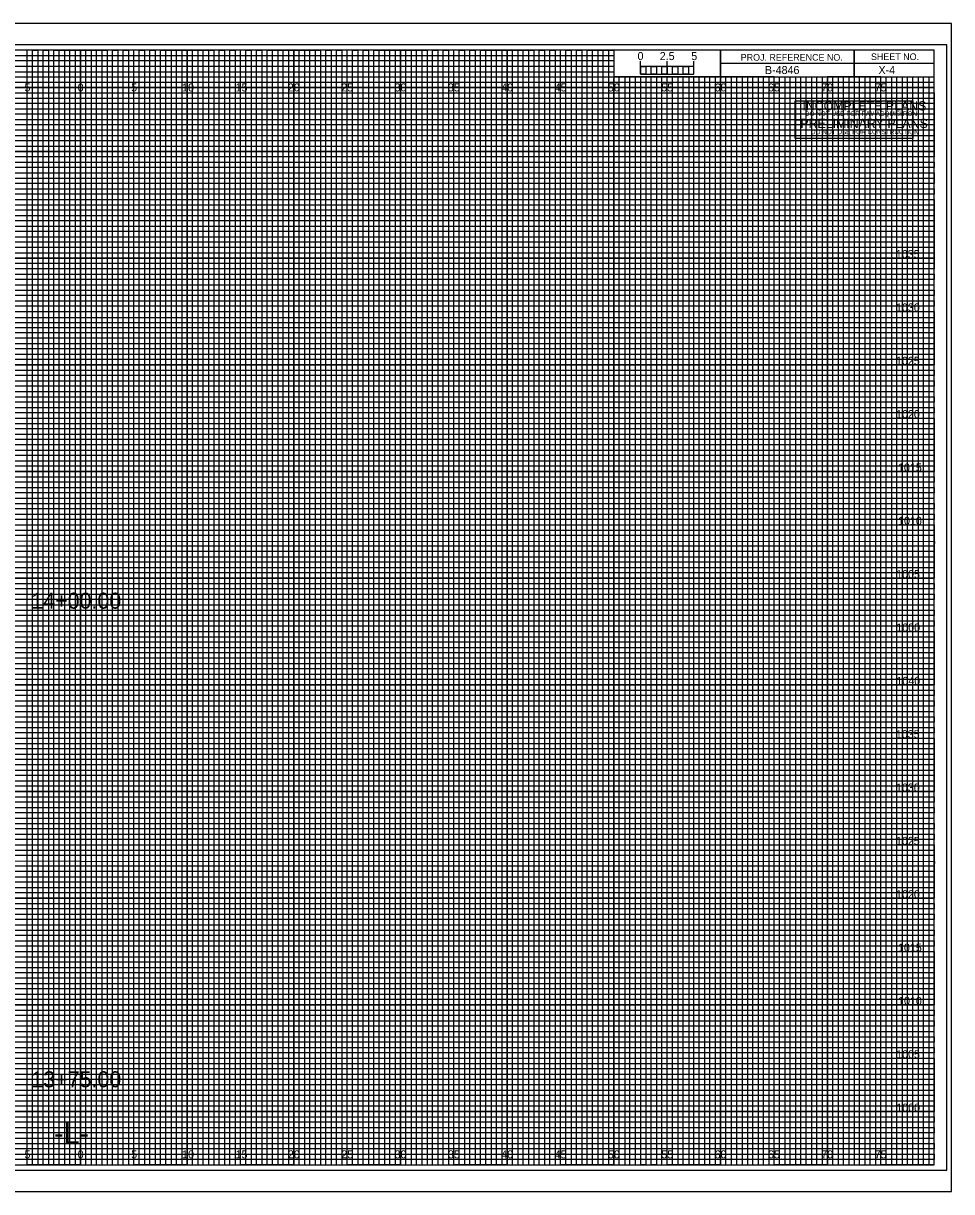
# Model space of a CAD drawing. Extents: x -7 to 162, y -2 to 987.
# Drawn here: x 74.6 to 161.7, y 327.5 to 437 of the extents above; entities that cross this region are included whole.
import ezdxf

# ---------------------------------------------------------------- set-up
doc = ezdxf.new("R2010")
doc.units = 0
for name, color, linetype in [('Default', 7, 'Continuous'), ('Exist Cross Section Cell', 7, 'Continuous'), ('Exist XS Center Line Elevation Label', 7, 'Continuous'), ('Exist XS Ground Line', 7, 'Continuous'), ('Prop CMT Concrete Structures', 7, 'Continuous'), ('Prop CMT DNC', 7, 'Continuous'), ('Prop CMT Guardrail Graphics', 7, 'Continuous'), ('Prop CMT Guardrail Widen Shoulder', 7, 'Continuous'), ('Prop CMT Pvmt Course 1', 7, 'Continuous'), ('Prop CMT Pvmt Surface', 7, 'Continuous'), ('Prop CMT Pvmt Surface Shoulder', 7, 'Continuous'), ('Prop CMT Shld Paved Course 1', 7, 'Continuous'), ('Prop CMT Shoulder Point', 7, 'Continuous'), ('Prop CMT Slope Grass', 7, 'Continuous'), ('Prop CMT Subgrade Earthwork', 7, 'Continuous'), ('Prop XS SE Text', 7, 'Continuous'), ('Prop XS Side Slope Text', 7, 'Continuous'), ('Typical Text Label CELL', 7, 'Continuous')]:
    doc.layers.add(name, color=color, linetype=linetype)

msp = doc.modelspace()

# ---------------------------------------------------------------- linework, layer by layer
at = {"layer": 'Default'}
for points in [[(146.99, 427.97), (146.99, 429.73), (158.01, 429.73), (158.01, 427.97)], [(146.99, 426.2), (146.99, 427.97), (158.01, 427.97), (158.01, 426.2)]]:
    msp.add_lwpolyline(points, close=True, dxfattribs=at)
at = {"layer": 'Exist XS Center Line Elevation Label'}
for points in [[(72.5, 330), (77.5, 330), (77.5, 434.5), (82.5, 434.5), (82.5, 330), (87.5, 330), (87.5, 434.5), (92.5, 434.5), (92.5, 330), (97.5, 330), (97.5, 434.5), (102.5, 434.5), (102.5, 330), (107.5, 330), (107.5, 434.5), (112.5, 434.5), (112.5, 330), (117.5, 330), (117.5, 434.5), (122.5, 434.5), (122.5, 330), (127.5, 330), (127.5, 434.5), (129.97, 434.5), (130, 434.5), (130, 432), (132.5, 432), (132.5, 330), (137.5, 330), (137.5, 432), (142.5, 432), (142.5, 330), (147.5, 330), (147.5, 432), (152.5, 432), (152.5, 330), (157.5, 330), (157.5, 432)], [(0, 432), (137.5, 432)], [(0, 422.5), (160, 422.5), (160, 427.5), (0, 427.5)], [(0, 412.5), (160, 412.5), (160, 417.5), (0, 417.5)], [(0, 402.5), (160, 402.5), (160, 407.5), (0, 407.5)], [(0, 392.5), (160, 392.5), (160, 397.5), (0, 397.5)], [(0, 382.5), (160, 382.5), (160, 387.5), (0, 387.5)], [(0, 372.5), (160, 372.5), (160, 377.5), (0, 377.5)], [(0, 362.5), (160, 362.5), (160, 367.5), (0, 367.5)], [(0, 352.5), (160, 352.5), (160, 357.5), (0, 357.5)], [(0, 342.5), (160, 342.5), (160, 347.5), (0, 347.5)], [(0, 332.5), (160, 332.5), (160, 337.5), (0, 337.5)]]:
    msp.add_lwpolyline(points, dxfattribs=at)
at = {"layer": 'Exist XS Ground Line'}
for p, q in [((75, 434.5), (70, 434.5)), ((75, 330), (75, 434.5)), ((85, 434.5), (80, 434.5)), ((80, 434.5), (80, 330)), ((85, 330), (85, 434.5)), ((95, 434.5), (90, 434.5)), ((90, 434.5), (90, 330)), ((95, 330), (95, 434.5)), ((105, 434.5), (100, 434.5)), ((100, 434.5), (100, 330)), ((105, 330), (105, 434.5)), ((115, 434.5), (110, 434.5)), ((110, 434.5), (110, 330)), ((115, 330), (115, 434.5)), ((125, 434.5), (120, 434.5)), ((120, 434.5), (120, 330)), ((125, 330), (125, 434.5)), ((130, 434.5), (130, 330)), ((135, 330), (135, 432)), ((145, 432), (140, 432)), ((140, 432), (140, 330)), ((145, 330), (145, 432)), ((155, 432), (150, 432)), ((150, 432), (150, 330)), ((155, 330), (155, 432)), ((80, 330), (75, 330)), ((90, 330), (85, 330)), ((100, 330), (95, 330)), ((110, 330), (105, 330)), ((120, 330), (115, 330)), ((130, 330), (125, 330)), ((140, 330), (135, 330)), ((150, 330), (145, 330)), ((160, 330), (155, 330)), ((160, 330), (160, 330))]:
    msp.add_line(p, q, dxfattribs=at)
for points in [[(0, 430), (160, 430), (160, 425), (0, 425)], [(0, 420), (160, 420), (160, 415), (0, 415)], [(0, 410), (160, 410), (160, 405), (0, 405)], [(0, 400), (160, 400), (160, 395), (0, 395)], [(0, 390), (160, 390), (160, 385), (0, 385)], [(0, 380), (160, 380), (160, 375), (0, 375)], [(0, 370), (160, 370), (160, 365), (0, 365)], [(0, 360), (160, 360), (160, 355), (0, 355)], [(0, 350), (160, 350), (160, 345), (0, 345)], [(0, 340), (160, 340), (160, 335), (0, 335)]]:
    msp.add_lwpolyline(points, dxfattribs=at)
at = {"layer": 'Prop CMT Concrete Structures'}
for p, q in [((75, 330), (75, 434.5)), ((80, 330), (80, 434.5)), ((85, 330), (85, 434.5)), ((90, 330), (90, 434.5)), ((95, 330), (95, 434.5)), ((100, 330), (100, 434.5)), ((105, 330), (105, 434.5)), ((110, 330), (110, 434.5)), ((115, 330), (115, 434.5)), ((120, 330), (120, 434.5)), ((125, 330), (125, 434.5)), ((130, 330), (130, 431.84)), ((135, 330), (135, 431.84)), ((140, 330), (140, 431.84)), ((145, 330), (145, 431.84)), ((150, 330), (150, 431.84)), ((155, 330), (155, 431.84)), ((0, 430), (160, 430)), ((0, 425), (160, 425)), ((0, 420), (160, 420)), ((0, 415), (160, 415)), ((0, 410), (160, 410)), ((0, 405), (160, 405)), ((0, 400), (160, 400)), ((0, 395), (160, 395)), ((0, 390), (160, 390)), ((0, 385), (160, 385)), ((0, 380), (160, 380)), ((0, 375), (160, 375)), ((0, 370), (160, 370)), ((0, 365), (160, 365)), ((0, 360), (160, 360)), ((0, 355), (160, 355)), ((0, 350), (160, 350)), ((0, 345), (160, 345)), ((0, 340), (160, 340)), ((0, 335), (160, 335))]:
    msp.add_line(p, q, dxfattribs=at)
at = {"layer": 'Prop CMT Guardrail Widen Shoulder'}
for p, q in [((161.65, 437), (-6.7, 437)), ((-6.7, 327.5), (161.65, 327.5))]:
    msp.add_line(p, q, dxfattribs=at)
at = {"layer": 'Prop CMT Pvmt Course 1'}
msp.add_lwpolyline([(-6.7, 327.5), (161.65, 327.5), (161.65, 437), (-6.7, 437)], close=True, dxfattribs=at)
at = {"layer": 'Prop CMT Pvmt Surface'}
for p, q in [((133.5, 432), (133, 432)), ((133, 432), (133, 330)), ((133.5, 330), (133.5, 432)), ((134.5, 432), (134, 432)), ((134, 432), (134, 330)), ((134.5, 330), (134.5, 432)), ((133, 330), (132.5, 330)), ((134, 330), (133.5, 330))]:
    msp.add_line(p, q, dxfattribs=at)
for points in [[(75, 330), (75.5, 330), (75.5, 434.5), (76, 434.5), (76, 330)], [(76, 330), (76.5, 330), (76.5, 434.5), (77, 434.5), (77, 330)], [(77.5, 330), (78, 330), (78, 434.5), (78.5, 434.5), (78.5, 330)], [(78.5, 330), (79, 330), (79, 434.5), (79.5, 434.5), (79.5, 330)], [(80, 330), (80.5, 330), (80.5, 434.5), (81, 434.5), (81, 330)], [(81, 330), (81.5, 330), (81.5, 434.5), (82, 434.5), (82, 330)], [(82.5, 330), (83, 330), (83, 434.5), (83.5, 434.5), (83.5, 330)], [(83.5, 330), (84, 330), (84, 434.5), (84.5, 434.5), (84.5, 330)], [(85, 330), (85.5, 330), (85.5, 434.5), (86, 434.5), (86, 330)], [(86, 330), (86.5, 330), (86.5, 434.5), (87, 434.5), (87, 330)], [(87.5, 330), (88, 330), (88, 434.5), (88.5, 434.5), (88.5, 330)], [(88.5, 330), (89, 330), (89, 434.5), (89.5, 434.5), (89.5, 330)], [(90, 330), (90.5, 330), (90.5, 434.5), (91, 434.5), (91, 330)], [(91, 330), (91.5, 330), (91.5, 434.5), (92, 434.5), (92, 330)], [(92.5, 330), (93, 330), (93, 434.5), (93.5, 434.5), (93.5, 330)], [(93.5, 330), (94, 330), (94, 434.5), (94.5, 434.5), (94.5, 330)], [(95, 330), (95.5, 330), (95.5, 434.5), (96, 434.5), (96, 330)], [(96, 330), (96.5, 330), (96.5, 434.5), (97, 434.5), (97, 330)], [(97.5, 330), (98, 330), (98, 434.5), (98.5, 434.5), (98.5, 330)], [(98.5, 330), (99, 330), (99, 434.5), (99.5, 434.5), (99.5, 330)], [(100, 330), (100.5, 330), (100.5, 434.5), (101, 434.5), (101, 330)], [(101, 330), (101.5, 330), (101.5, 434.5), (102, 434.5), (102, 330)], [(102.5, 330), (103, 330), (103, 434.5), (103.5, 434.5), (103.5, 330)], [(103.5, 330), (104, 330), (104, 434.5), (104.5, 434.5), (104.5, 330)], [(105, 330), (105.5, 330), (105.5, 434.5), (106, 434.5), (106, 330)], [(106, 330), (106.5, 330), (106.5, 434.5), (107, 434.5), (107, 330)], [(107.5, 330), (108, 330), (108, 434.5), (108.5, 434.5), (108.5, 330)], [(108.5, 330), (109, 330), (109, 434.5), (109.5, 434.5), (109.5, 330)], [(110, 330), (110.5, 330), (110.5, 434.5), (111, 434.5), (111, 330)], [(111, 330), (111.5, 330), (111.5, 434.5), (112, 434.5), (112, 330)], [(112.5, 330), (113, 330), (113, 434.5), (113.5, 434.5), (113.5, 330)], [(113.5, 330), (114, 330), (114, 434.5), (114.5, 434.5), (114.5, 330)], [(115, 330), (115.5, 330), (115.5, 434.5), (116, 434.5), (116, 330)], [(116, 330), (116.5, 330), (116.5, 434.5), (117, 434.5), (117, 330)], [(117.5, 330), (118, 330), (118, 434.5), (118.5, 434.5), (118.5, 330)], [(118.5, 330), (119, 330), (119, 434.5), (119.5, 434.5), (119.5, 330)], [(120, 330), (120.5, 330), (120.5, 434.5), (121, 434.5), (121, 330)], [(121, 330), (121.5, 330), (121.5, 434.5), (122, 434.5), (122, 330)], [(122.5, 330), (123, 330), (123, 434.5), (123.5, 434.5), (123.5, 330)], [(123.5, 330), (124, 330), (124, 434.5), (124.5, 434.5), (124.5, 330)], [(125, 330), (125.5, 330), (125.5, 434.5), (126, 434.5), (126, 330)], [(126, 330), (126.5, 330), (126.5, 434.5), (127, 434.5), (127, 330)], [(127.5, 330), (128, 330), (128, 434.5), (128.5, 434.5), (128.5, 330)], [(128.5, 330), (129, 330), (129, 434.5), (129.5, 434.5), (129.5, 330)], [(130, 330), (130.5, 330), (130.5, 432), (131.01, 432), (131.01, 330)], [(131, 330), (131.5, 330), (131.5, 432), (132, 432), (132, 330)], [(135, 330), (135.49, 330), (135.49, 432), (136, 432), (136, 330)], [(136, 330), (136.5, 330), (136.5, 432), (137.03, 432), (137.03, 330)], [(137.5, 330), (138, 330), (138, 432), (138.5, 432), (138.5, 330)], [(138.5, 330), (139, 330), (139, 432), (139.5, 432), (139.5, 330)], [(140, 330), (140.5, 330), (140.5, 432), (141, 432), (141, 330)], [(141, 330), (141.5, 330), (141.5, 432), (142, 432), (142, 330)], [(142.5, 330), (143, 330), (143, 432), (143.5, 432), (143.5, 330)], [(143.5, 330), (144, 330), (144, 432), (144.5, 432), (144.5, 330)], [(145, 330), (145.5, 330), (145.5, 432), (146, 432), (146, 330)], [(146, 330), (146.5, 330), (146.5, 432), (147, 432), (147, 330)], [(147.5, 330), (148, 330), (148, 432), (148.5, 432), (148.5, 330)], [(148.5, 330), (149, 330), (149, 432), (149.5, 432), (149.5, 330)], [(150, 330), (150.5, 330), (150.5, 432), (151, 432), (151, 330)], [(151, 330), (151.5, 330), (151.5, 432), (152, 432), (152, 330)], [(152.5, 330), (153, 330), (153, 432), (153.5, 432), (153.5, 330)], [(153.5, 330), (154, 330), (154, 432), (154.5, 432), (154.5, 330)], [(155, 330), (155.5, 330), (155.5, 432), (156, 432), (156, 330)], [(156, 330), (156.5, 330), (156.5, 432), (157, 432), (157, 330)], [(157.5, 330), (158, 330), (158, 432), (158.5, 432), (158.5, 330)], [(158.5, 330), (159, 330), (159, 432), (159.5, 432), (159.5, 330)]]:
    msp.add_lwpolyline(points, dxfattribs=at)
at = {"layer": 'Prop CMT Pvmt Surface Shoulder'}
for p, q in [((132.5, 432.25), (132.5, 433.45)), ((132.5, 432.95), (132.5, 433.45)), ((135, 432.25), (135, 433.45)), ((137.5, 432.25), (137.5, 433.45)), ((137.5, 432.95), (137.5, 433.45))]:
    msp.add_line(p, q, dxfattribs=at)
for points in [[(137.5, 432.95), (132.5, 432.95), (132.5, 432.25), (137.5, 432.25)], [(132.5, 432.95), (133, 432.95), (133, 432.25), (132.5, 432.25)], [(133.5, 432.95), (134, 432.95), (134, 432.25), (133.5, 432.25)], [(134.5, 432.95), (135, 432.95), (135, 432.25), (134.5, 432.25)], [(135.5, 432.95), (136, 432.95), (136, 432.25), (135.5, 432.25)], [(136.5, 432.95), (137, 432.95), (137, 432.25), (136.5, 432.25)]]:
    msp.add_lwpolyline(points, close=True, dxfattribs=at)
at = {"layer": 'Prop CMT Shld Paved Course 1'}
for p, q in [((0, 434), (130, 434)), ((130, 434), (130, 433.49)), ((130, 433.49), (0, 433.49)), ((0, 433), (130, 433)), ((130, 433), (130, 432.44)), ((130, 432.44), (0, 432.44)), ((0, 431.5), (160, 431.5))]:
    msp.add_line(p, q, dxfattribs=at)
for points in [[(0, 431), (135, 431), (160, 431), (160, 431), (0, 431)], [(0, 430.5), (160, 430.5), (160, 429.5), (0, 429.5)], [(0, 429), (160, 429), (160, 428.5), (0, 428.49)], [(0, 428), (160, 428), (160, 427), (0, 427)], [(0, 426.5), (160, 426.5), (160, 426), (0, 426)], [(0, 425.5), (160, 425.5), (160, 424.5), (0, 424.5)], [(0, 424), (160, 424), (160, 423.5), (0, 423.5)], [(0, 423), (160, 423), (160, 422), (0, 422)], [(0, 421.5), (160, 421.5), (160, 421), (0, 421)], [(0, 420.5), (160, 420.5), (160, 419.5), (0, 419.5)], [(0, 419), (160, 419), (160, 418.5), (0, 418.5)], [(0, 418), (160, 418), (160, 416.98), (160, 416.5), (160, 416), (0, 416)], [(0, 417), (160, 417), (160, 416.5), (0, 416.5)], [(0, 415.5), (160, 415.5), (160, 414.5), (0, 414.51)], [(0, 414.51), (160, 414.5), (160, 414), (0, 414)], [(0, 413.5), (160, 413.5), (160, 413), (0, 413)], [(0, 412), (160, 412), (160, 411.5), (0, 411.5)], [(0, 411), (160, 411), (160, 410.5), (0, 410.5)], [(-0.04, 409.44), (160, 409.44), (160, 408.94), (-0.04, 408.94)], [(0, 408.5), (160, 408.5), (160, 408), (0, 408)], [(0, 407), (160, 407), (160, 406.5), (0, 406.5)], [(0, 406), (160, 406), (160, 405.5), (0, 405.5)], [(0, 404.5), (160, 404.5), (160, 404), (0, 404)], [(0, 403.5), (160, 403.5), (160, 403), (0, 403)], [(0, 402), (160, 402), (160, 401.5), (0, 401.5)], [(0, 401), (160, 401), (160, 400.5), (0, 400.5)], [(0, 399.5), (160, 399.5), (160, 398.99), (0, 399)], [(0, 398.5), (160, 398.5), (160, 398), (0, 398)], [(0, 397), (160, 397), (160, 396.5), (0, 396.5)], [(0, 396), (160, 396), (160, 395.5), (0, 395.5)], [(0, 394.5), (160, 394.5), (160, 394), (0, 394)], [(0, 393.5), (160, 393.5), (160, 393), (0, 393)], [(0, 392), (160, 392), (160, 391.5), (0, 391.5)], [(0, 391), (160, 391), (160, 390.5), (0, 390.5)], [(0, 389.5), (160, 389.5), (160, 389), (0, 389)], [(0, 388.5), (160.03, 388.45), (160, 388), (0, 388)], [(0, 387), (160, 387), (160, 386.5), (0, 386.5)], [(0, 386), (160, 386), (160, 385.5), (0, 385.5)], [(0, 384.5), (160, 384.5), (160, 384), (0, 384)], [(0, 383.5), (160, 383.5), (160, 383), (0, 383)], [(0, 382), (160, 382), (160, 381.5), (0, 381.5)], [(0, 381), (160, 381), (160, 380.5), (0, 380.5)], [(0, 379.5), (160, 379.5), (160, 379), (0, 379)], [(0, 378.5), (160, 378.5), (160, 378), (0, 378)], [(0, 377), (160, 377), (160, 376.5), (0, 376.5)], [(0, 376), (160, 376), (160, 375.5), (0, 375.5)], [(0, 374.5), (160, 374.5), (160, 374), (0, 374)], [(0, 373.5), (160, 373.5), (160, 373), (0, 373)], [(0, 372), (160, 372), (160, 371.5), (0, 371.5)], [(0, 371), (160, 371), (160, 370.5), (0, 370.5)], [(0, 369.5), (160, 369.5), (160, 368.99), (0, 369)], [(0, 368.5), (160, 368.5), (160, 368), (0, 368)], [(0, 367), (160, 367), (160, 366.5), (0, 366.5)], [(0, 366), (160, 366), (160, 365.5), (0, 365.5)], [(0, 364.5), (160, 364.5), (160, 364), (0, 364)], [(0, 363.5), (160, 363.5), (160, 363), (0, 363)], [(0, 362), (160, 362), (160, 361.5), (0, 361.5)], [(0, 361), (160, 361), (160, 360.5), (0, 360.5)], [(0, 359.5), (160, 359.5), (160, 359), (0, 359)], [(0, 358.5), (160.03, 358.45), (160, 358), (0, 358)], [(0, 357), (160, 357), (160, 356.5), (0, 356.5)], [(0, 356), (160, 356), (160, 355.5), (0, 355.5)], [(0, 354.5), (160, 354.5), (160, 354), (0, 354)], [(0, 353.5), (160, 353.5), (160, 353), (0, 353)], [(0, 352), (160, 352), (160, 351.5), (0, 351.5)], [(0, 351), (160, 351), (160, 350.5), (0, 350.5)], [(0, 349.5), (160, 349.5), (160, 349), (0, 349)], [(0, 348.5), (160, 348.5), (160, 348), (0, 348)], [(0, 347), (160, 347), (160, 346.5), (0, 346.5)], [(0, 346), (160, 346), (160, 345.5), (0, 345.5)], [(0, 344.5), (160, 344.5), (160, 344), (0, 344)], [(0, 343.5), (160, 343.5), (160, 343), (0, 343)], [(0, 342), (160, 342), (160, 341.5), (0, 341.5)], [(0, 341), (160, 341), (160, 340.5), (0, 340.5)], [(0, 339.5), (160, 339.5), (160, 339), (0, 339)], [(0, 338.5), (160, 338.5), (160, 338), (0, 338)], [(0, 337), (160, 337), (160, 336.5), (0, 336.5)], [(0, 336), (160, 336), (160, 335.5), (0, 335.5)], [(0, 334.5), (160, 334.5), (160, 334), (0, 334)], [(0, 333.5), (160, 333.5), (160, 333), (0, 333)], [(0, 332), (160, 332), (160, 331.5), (0, 331.5)], [(0, 331), (160, 331), (160, 330.5), (0, 330.5)]]:
    msp.add_lwpolyline(points, dxfattribs=at)
at = {"layer": 'Prop CMT Slope Grass'}
msp.add_lwpolyline([(-5.4, 329.5), (161.2, 329.5), (161.2, 435), (-5.4, 435)], close=True, dxfattribs=at)
at = {"layer": 'Prop CMT Subgrade Earthwork'}
for p, q in [((152.5, 434.5), (152.5, 432)), ((152.5, 432), (152.5, 434.5)), ((160, 433.25), (140, 433.25)), ((140, 433.25), (140, 432)), ((140, 432), (160, 432))]:
    msp.add_line(p, q, dxfattribs=at)
for points in [[(160, 434.5), (0, 434.5), (0, 330), (160, 330)], [(140, 434.5), (130, 434.5), (130, 432.01), (140, 432.01)], [(160, 434.5), (140, 434.5), (140, 432), (160, 432)]]:
    msp.add_lwpolyline(points, close=True, dxfattribs=at)

# ---------------------------------------------------------------- texts
at = {"layer": 'Default'}
for s, height, p in [('INCOMPLETE PLANS', 0.864, (147.66, 428.84)), ('DO NOT USE FOR R/W ACQUISITION', 0.432, (147.9, 428.32)), ('PRELIMINARY PLANS', 0.864, (147.47, 427.19)), ('DO NOT USE FOR CONSTRUCTION', 0.432, (148.46, 426.61))]:
    msp.add_text(s, height=height, dxfattribs=at).set_placement(p)
at = {"layer": 'Exist Cross Section Cell'}
for s, p in [('5', (74.74, 430.62)), ('0', (79.73, 430.62)), ('0', (79.73, 430.62)), ('5', (84.74, 430.62)), ('10', (89.52, 430.62)), ('15', (94.53, 430.62)), ('20', (99.43, 430.62)), ('25', (104.44, 430.62)), ('30', (109.43, 430.62)), ('35', (114.44, 430.62)), ('40', (119.43, 430.62)), ('45', (124.44, 430.62)), ('50', (129.43, 430.62)), ('55', (134.44, 430.62)), ('60', (139.43, 430.62)), ('65', (144.44, 430.62)), ('70', (149.43, 430.62)), ('75', (154.44, 430.62)), ('5', (74.74, 330.62)), ('0', (79.73, 330.62)), ('0', (79.73, 330.62)), ('5', (84.74, 330.62)), ('10', (89.52, 330.62)), ('15', (94.53, 330.62)), ('20', (99.43, 330.62)), ('25', (104.44, 330.62)), ('30', (109.43, 330.62)), ('35', (114.44, 330.62)), ('40', (119.43, 330.62)), ('45', (124.44, 330.62)), ('50', (129.43, 330.62)), ('55', (134.44, 330.62)), ('60', (139.43, 330.62)), ('65', (144.44, 330.62)), ('70', (149.43, 330.62)), ('75', (154.44, 330.62))]:
    msp.add_text(s, height=0.75, dxfattribs=at).set_placement(p)
at = {"layer": 'Prop CMT DNC'}
msp.add_text('-L-', height=2, dxfattribs=at).set_placement((77.53, 332))
at = {"layer": 'Prop CMT Guardrail Graphics'}
msp.add_text('B-4846', height=0.75, dxfattribs=at).set_placement((144.15, 432.25))
at = {"layer": 'Prop CMT Pvmt Surface Shoulder'}
msp.add_text('0', height=0.75, dxfattribs=at).set_placement((132.21, 433.56))
at = {"layer": 'Prop CMT Shoulder Point'}
for s, p in [('2.5', (134.29, 433.56)), ('5', (137.24, 433.56))]:
    msp.add_text(s, height=0.75, dxfattribs=at).set_placement(p)
at = {"layer": 'Prop CMT Subgrade Earthwork'}
for s, p in [('PROJ. REFERENCE NO.', (141.88, 433.5)), ('SHEET NO.', (154.09, 433.56))]:
    msp.add_text(s, height=0.625, dxfattribs=at).set_placement(p)
at = {"layer": 'Prop XS SE Text'}
msp.add_text('X-4', height=0.75, dxfattribs=at).set_placement((154.79, 432.25))
at = {"layer": 'Prop XS Side Slope Text'}
for s, p in [('14+00.00', (75.39, 382.14)), ('13+75.00', (75.39, 337.28))]:
    msp.add_text(s, height=1.5, dxfattribs=at).set_placement(p)
at = {"layer": 'Typical Text Label CELL'}
for s, p in [('1035', (156.42, 415)), ('1030', (156.43, 410)), ('1025', (156.43, 405)), ('1020', (156.44, 400)), ('1015', (156.62, 395)), ('1010', (156.63, 390)), ('1005', (156.45, 385)), ('1000', (156.46, 380)), ('1040', (156.47, 375)), ('1035', (156.42, 370)), ('1030', (156.43, 365)), ('1025', (156.43, 360)), ('1020', (156.44, 355)), ('1015', (156.62, 350)), ('1010', (156.63, 345)), ('1005', (156.45, 340)), ('1000', (156.46, 335))]:
    msp.add_text(s, height=0.75, dxfattribs=at).set_placement(p)

doc.saveas('drawing.dxf')
